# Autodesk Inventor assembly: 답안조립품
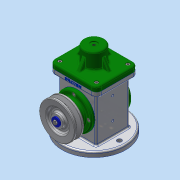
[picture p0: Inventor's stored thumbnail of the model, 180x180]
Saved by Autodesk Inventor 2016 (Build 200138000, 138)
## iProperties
Created: 2018-10
Part Number: 답안조립품
Material: 일반
Document SubType Name: Assembly
Designer: 3sil_cad018
Author: 3sil_cad018
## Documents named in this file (18)
- C:\Users\3sil_cad018\Desktop\481008V1006\답안조립품.iam
- C:\Users\3sil_cad018\Desktop\481008V1006\본체.ipt
- C:\Users\3sil_cad018\Desktop\481008V1006\뒤커버.ipt
- C:\Users\3sil_cad018\Desktop\481008V1006\링크.ipt
- C:\Users\3sil_cad018\Desktop\481008V1006\베어링 17 x 40 x 12.ipt
- C:\Users\3sil_cad018\Desktop\481008V1006\볼트 M4 x 8.ipt
- C:\Users\3sil_cad018\Desktop\481008V1006\볼트 M4 x 10.ipt
- C:\Users\3sil_cad018\Desktop\481008V1006\슬라이더.ipt
- C:\Users\3sil_cad018\Desktop\481008V1006\앞커버.ipt
- C:\Users\3sil_cad018\Desktop\481008V1006\오일 실 17 30 8.ipt
- C:\Users\3sil_cad018\Desktop\481008V1006\와셔 4x16.ipt
- C:\Users\3sil_cad018\Desktop\481008V1006\클레비스 핀 6 x 22.ipt
- 클레비스 핀 6 x 22.ipt
- C:\Users\3sil_cad018\Desktop\481008V1006\키 4 x 4 x 12.ipt
- C:\Users\3sil_cad018\Desktop\481008V1006\편심축.ipt
- C:\Users\3sil_cad018\Desktop\481008V1006\E-링.ipt
- C:\Users\3sil_cad018\Desktop\481008V1006\V-벨트풀리.ipt
- C:\Users\3sil_cad018\Desktop\481008V1006\덮개.ipt
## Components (2 placed, 2 different names)
1. E-링:1
2. V-벨트풀리:1 — 각도:2
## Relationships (1: Angle 1)
- 각도:2 [Angle]: V-벨트풀리:1
